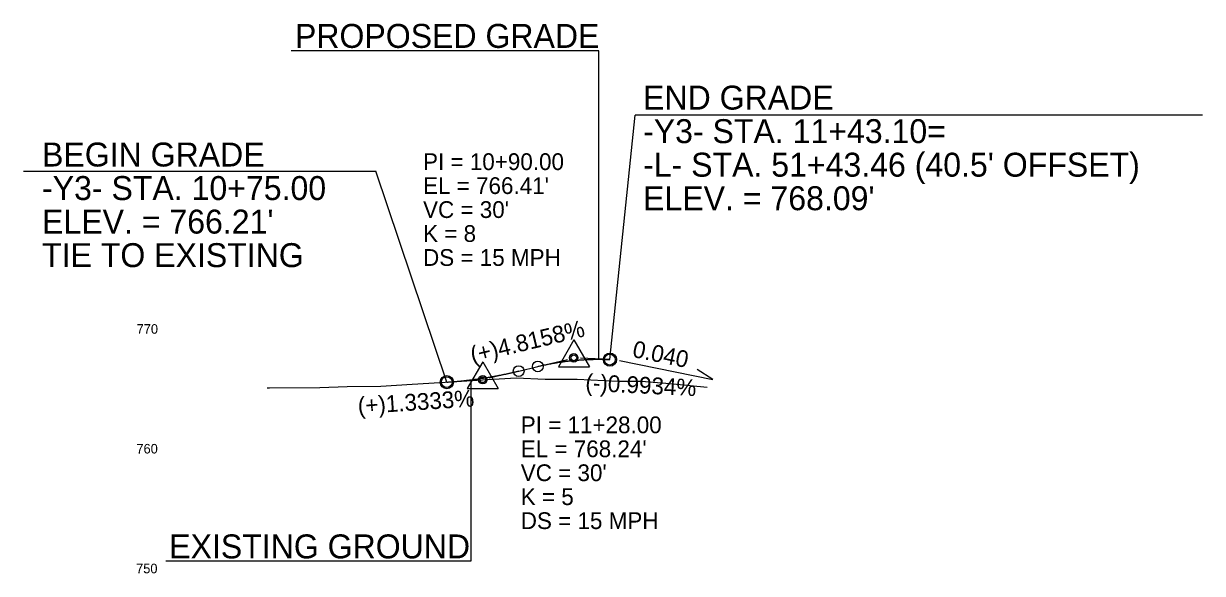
# Model space of a CAD drawing. Extents: x 1554255 to 1803987, y 659549 to 692876.
# Drawn here: x 1554701.2 to 1555193.2, y 689560.5 to 689790 of the extents above; entities that cross this region are included whole.
import ezdxf

# ---------------------------------------------------------------- set-up
doc = ezdxf.new("R2010")
doc.units = 0
for name, color, linetype in [('Default', 7, 'Continuous'), ('Exist Vertical Profile Ground Line', 7, 'Continuous'), ('Prop PFL Text', 7, 'Continuous'), ('Prop PFL VPI Symbol CELL', 7, 'Continuous'), ('Prop Vertical Profile Curve Label', 7, 'Continuous'), ('Prop Vertical Profile Grade', 7, 'Continuous'), ('Prop Vertical Profile Grade Label', 7, 'Continuous'), ('Prop VPI Label', 7, 'Continuous')]:
    doc.layers.add(name, color=color, linetype=linetype)

msp = doc.modelspace()

# ---------------------------------------------------------------- linework, layer by layer
at = {"layer": 'Exist Vertical Profile Ground Line'}
msp.add_lwpolyline([(1554802.85, 689637.89), (1554803.91, 689637.94), (1554824.92, 689638.01), (1554836.32, 689638.53), (1554850.33, 689638.64), (1554863.42, 689639.51), (1554879.49, 689640.42), (1554894.99, 689641.45), (1554906.77, 689642.12), (1554918.86, 689641.55), (1554932.22, 689641.54), (1554949.31, 689640.71), (1554959.31, 689640.7), (1554962.29, 689640.41), (1554970.92, 689639.69), (1554986.46, 689638.22)], dxfattribs=at)
at = {"layer": 'Prop PFL Text'}
for p, q in [((1554941.25, 689778.62), (1554812.95, 689778.62)), ((1554941.25, 689649.84), (1554941.25, 689778.62)), ((1554945.95, 689649.71), (1554956.45, 689751.78)), ((1555193.2, 689751.78), (1554956.45, 689751.78)), ((1554701.22, 689728.38), (1554848.22, 689728.38)), ((1554877.85, 689640.31), (1554848.22, 689728.38)), ((1554887.85, 689640.97), (1554887.85, 689565.51)), ((1554887.85, 689565.51), (1554760.6, 689565.51))]:
    msp.add_line(p, q, dxfattribs=at)
at = {"layer": 'Prop PFL VPI Symbol CELL'}
for p, q in [((1554930.85, 689657.94), (1554924.4, 689646.74)), ((1554930.85, 689657.94), (1554937.35, 689646.74)), ((1554892.85, 689648.79), (1554886.4, 689637.59)), ((1554892.85, 689648.79), (1554899.35, 689637.59)), ((1554924.4, 689646.74), (1554937.35, 689646.74)), ((1554886.4, 689637.59), (1554899.35, 689637.59))]:
    msp.add_line(p, q, dxfattribs=at)
for centre, radius in [((1554930.85, 689650.46), 1.75), ((1554930.85, 689650.46), 1.2), ((1554892.85, 689641.31), 1.75), ((1554892.85, 689641.31), 1.2)]:
    msp.add_circle(centre, radius, dxfattribs=at)
at = {"layer": 'Prop Vertical Profile Curve Label'}
for centre in [(1554945.85, 689649.71), (1554907.85, 689644.92), (1554915.85, 689646.85), (1554877.85, 689640.31)]:
    msp.add_circle(centre, 2.25, dxfattribs=at)
at = {"layer": 'Prop Vertical Profile Grade'}
for p, q in [((1554907.85, 689644.92), (1554915.85, 689646.85)), ((1554945.85, 689649.71), (1554945.95, 689649.71))]:
    msp.add_line(p, q, dxfattribs=at)
for points in [[(1554915.85, 689646.85), (1554916.45, 689646.99), (1554917.05, 689647.13), (1554917.65, 689647.26), (1554918.25, 689647.4), (1554918.85, 689647.52), (1554919.45, 689647.65), (1554920.05, 689647.77), (1554920.65, 689647.89), (1554921.25, 689648), (1554921.85, 689648.12), (1554922.45, 689648.22), (1554923.05, 689648.33), (1554923.65, 689648.43), (1554924.25, 689648.53), (1554924.85, 689648.62), (1554925.45, 689648.71), (1554926.05, 689648.8), (1554926.65, 689648.88), (1554927.25, 689648.96), (1554927.85, 689649.04), (1554928.45, 689649.11), (1554929.05, 689649.18), (1554929.65, 689649.25), (1554930.25, 689649.31), (1554930.85, 689649.37), (1554931.45, 689649.42), (1554932.05, 689649.48), (1554932.65, 689649.52), (1554933.25, 689649.57), (1554933.85, 689649.61), (1554934.45, 689649.65), (1554935.05, 689649.68), (1554935.65, 689649.72), (1554936.25, 689649.74), (1554936.85, 689649.77), (1554937.45, 689649.79), (1554938.05, 689649.81), (1554938.65, 689649.82), (1554939.25, 689649.83), (1554939.85, 689649.84), (1554940.45, 689649.84), (1554941.05, 689649.84), (1554941.65, 689649.84), (1554942.25, 689649.83), (1554942.85, 689649.82), (1554943.45, 689649.8), (1554944.05, 689649.79), (1554944.65, 689649.76), (1554945.25, 689649.74), (1554945.85, 689649.71)], [(1554877.85, 689640.31), (1554878.45, 689640.35), (1554879.05, 689640.39), (1554879.65, 689640.44), (1554880.25, 689640.48), (1554880.85, 689640.53), (1554881.45, 689640.58), (1554882.05, 689640.64), (1554882.65, 689640.69), (1554883.25, 689640.75), (1554883.85, 689640.81), (1554884.45, 689640.87), (1554885.05, 689640.94), (1554885.65, 689641), (1554886.25, 689641.07), (1554886.85, 689641.14), (1554887.45, 689641.21), (1554888.05, 689641.29), (1554888.65, 689641.37), (1554889.25, 689641.44), (1554889.85, 689641.53), (1554890.45, 689641.61), (1554891.05, 689641.69), (1554891.65, 689641.78), (1554892.25, 689641.87), (1554892.85, 689641.96), (1554893.45, 689642.05), (1554894.05, 689642.15), (1554894.65, 689642.25), (1554895.25, 689642.35), (1554895.85, 689642.45), (1554896.45, 689642.55), (1554897.05, 689642.66), (1554897.65, 689642.76), (1554898.25, 689642.87), (1554898.85, 689642.99), (1554899.45, 689643.1), (1554900.05, 689643.22), (1554900.65, 689643.34), (1554901.25, 689643.46), (1554901.85, 689643.58), (1554902.45, 689643.7), (1554903.05, 689643.83), (1554903.65, 689643.96), (1554904.25, 689644.09), (1554904.85, 689644.22), (1554905.45, 689644.36), (1554906.05, 689644.5), (1554906.65, 689644.63), (1554907.25, 689644.78), (1554907.85, 689644.92)]]:
    msp.add_spline(points, degree=3, dxfattribs=at)
at = {"layer": 'Prop VPI Label'}
for p, q in [((1554915.85, 689646.85), (1554928.18, 689649.81)), ((1554945.85, 689649.71), (1554933.6, 689650.32)), ((1554949.96, 689649.39), (1554988.83, 689641.46)), ((1554907.85, 689644.92), (1554895.53, 689641.95)), ((1554988.83, 689641.46), (1554982.32, 689645.57)), ((1554877.85, 689640.31), (1554890.11, 689641.12))]:
    msp.add_line(p, q, dxfattribs=at)
for centre in [(1554945.95, 689649.71), (1554877.85, 689640.31)]:
    msp.add_circle(centre, 2.75, dxfattribs=at)

# ---------------------------------------------------------------- texts
at = {"layer": 'Default'}
for s, p in [('770', (1554748.41, 689660.51)), ('760', (1554748.32, 689610.51)), ('750', (1554748.19, 689560.51))]:
    msp.add_text(s, height=4, dxfattribs=at).set_placement(p)
at = {"layer": 'Prop PFL Text'}
for s, p in [('PROPOSED GRADE', (1554814.48, 689779.84)), ('END GRADE', (1554959.77, 689754.08)), ('-Y3- STA. 11+43.10=', (1554959.77, 689740.08)), ("-L- STA. 51+43.46 (40.5' OFFSET)", (1554959.77, 689726.08)), ("ELEV. = 768.09'", (1554959.77, 689712.08)), ('EXISTING GROUND', (1554762, 689566.73))]:
    msp.add_text(s, height=10, rotation=360, dxfattribs=at).set_placement(p)
for s, p in [('BEGIN GRADE', (1554708.93, 689730.32)), ('-Y3- STA. 10+75.00', (1554708.93, 689716.32)), ("ELEV. = 766.21'", (1554708.93, 689702.32)), ('TIE TO EXISTING', (1554708.93, 689688.32))]:
    msp.add_text(s, height=10, dxfattribs=at).set_placement(p)
at = {"layer": 'Prop Vertical Profile Grade Label'}
for s, rotation, p in [('(+)4.8158%', 13.5385, (1554888.62, 689648.13)), ('0.040', 348.3764, (1554954.96, 689650.89)), ('(-)0.9934%', 357.1565, (1554935.57, 689636.73)), ('(+)1.3333%', 3.8141, (1554840.93, 689626.93))]:
    msp.add_text(s, height=7, rotation=rotation, dxfattribs=at).set_placement(p)
at = {"layer": 'Prop VPI Label'}
for s, p in [('PI = 10+90.00', (1554867.94, 689728.84)), ("EL = 766.41'", (1554867.94, 689718.84)), ("VC = 30'", (1554867.94, 689708.84)), ('K = 8', (1554867.94, 689698.84)), ('DS = 15 MPH', (1554867.94, 689688.84)), ('PI = 11+28.00', (1554908.72, 689618.98)), ("EL = 768.24'", (1554908.72, 689608.98)), ("VC = 30'", (1554908.72, 689598.98)), ('K = 5', (1554908.72, 689588.98)), ('DS = 15 MPH', (1554908.72, 689578.98))]:
    msp.add_text(s, height=7, dxfattribs=at).set_placement(p)

doc.saveas('drawing.dxf')
